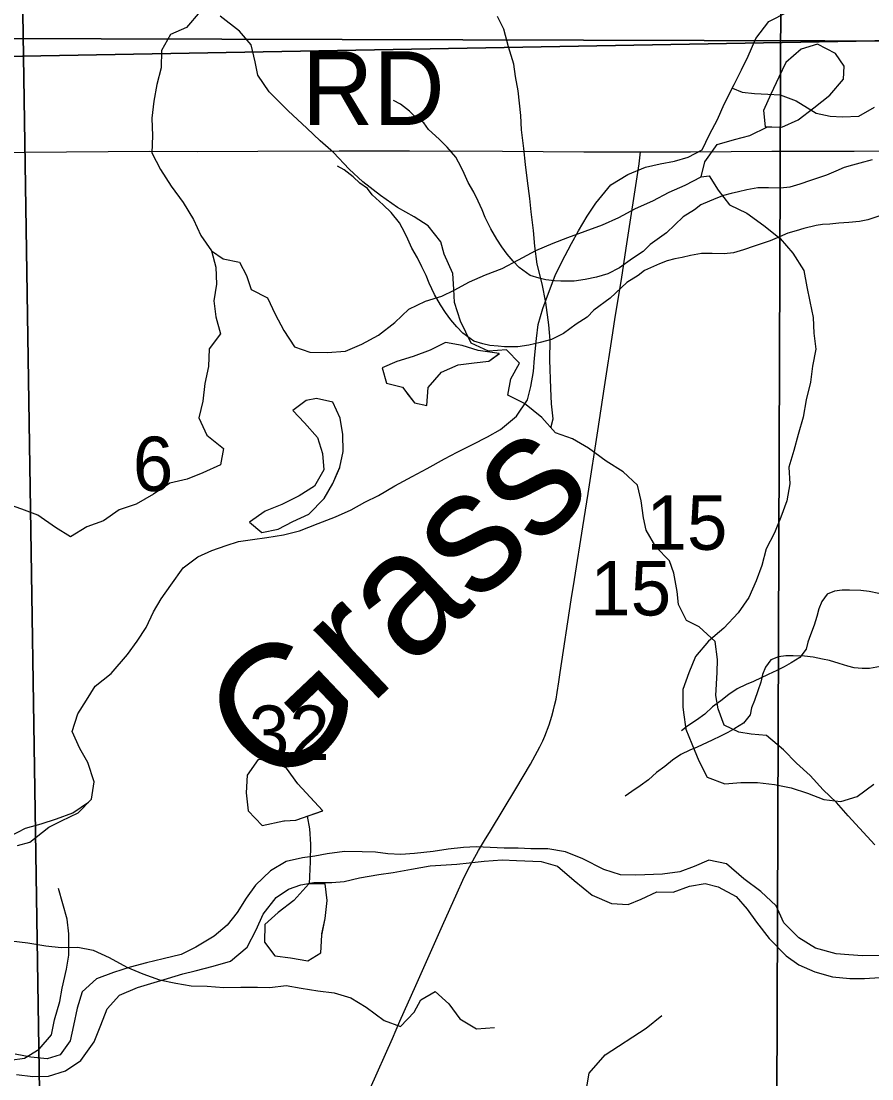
# Model space of a CAD drawing. Extents: x -21.1 to 50.3, y 0 to 22.1.
# Drawn here: x 5.83 to 6.485, y 16.143 to 16.957 of the extents above; entities that cross this region are included whole.
import ezdxf

# ---------------------------------------------------------------- set-up
doc = ezdxf.new("R2010")
doc.units = 0
for name, color, linetype in [('GM_X_Minor_Lake', 7, 'Continuous'), ('GM_X_Minor_River', 7, 'Continuous'), ('GM_X_Minor_River_Text', 7, 'Continuous'), ('GM_X_Section', 7, 'Continuous'), ('GM_X_Section_Text', 7, 'Continuous'), ('GM_X_Township_Road', 7, 'Continuous'), ('GM_X_Township_Road_Text', 7, 'Continuous')]:
    doc.layers.add(name, color=color, linetype=linetype)

msp = doc.modelspace()

# ---------------------------------------------------------------- linework, layer by layer
at = {"layer": 'GM_X_Minor_Lake'}
for points in [[(6.4637, 16.92197), (6.45706, 16.93166), (6.44297, 16.93887), (6.43042, 16.93505), (6.41864, 16.92477), (6.41333, 16.91335), (6.40726, 16.90042), (6.40157, 16.88786), (6.40273, 16.87532), (6.40788, 16.87519)], [(6.40788, 16.87519), (6.41567, 16.87496), (6.42821, 16.88067), (6.44038, 16.88982), (6.45254, 16.89972), (6.46317, 16.9119), (6.4637, 16.92197)], [(6.40788, 16.87517), (6.41567, 16.87496), (6.42821, 16.88067), (6.44038, 16.88982), (6.45254, 16.89972), (6.46317, 16.9119), (6.4637, 16.92197)], [(6.1982, 16.70081), (6.18192, 16.70317), (6.16974, 16.70696), (6.1568, 16.70923), (6.14501, 16.70351), (6.13208, 16.69855), (6.11953, 16.69473), (6.10813, 16.68978), (6.11157, 16.67799), (6.12375, 16.67496), (6.12713, 16.67047)], [(6.19822, 16.70081), (6.18192, 16.70317), (6.16974, 16.70696), (6.1568, 16.70923), (6.14501, 16.70351), (6.13208, 16.69855), (6.11953, 16.69473), (6.10813, 16.68978), (6.11157, 16.67799), (6.12375, 16.67496), (6.12713, 16.67047)], [(6.12708, 16.67042), (6.1329, 16.66281), (6.14241, 16.66092), (6.14353, 16.67461), (6.15379, 16.68641), (6.16672, 16.69213), (6.17889, 16.69367), (6.19031, 16.69482), (6.19829, 16.70088)], [(6.12713, 16.67047), (6.1329, 16.66281), (6.14241, 16.66092), (6.14353, 16.67461), (6.15379, 16.68641), (6.16672, 16.69213), (6.17889, 16.69367), (6.19031, 16.69482), (6.1982, 16.70081)], [(6.05765, 16.66625), (6.04957, 16.66461), (6.0393, 16.65699), (6.04845, 16.6475), (6.05836, 16.6361), (6.06218, 16.62394), (6.06335, 16.61139), (6.05613, 16.59883), (6.04435, 16.59122), (6.03104, 16.58473), (6.01811, 16.57939), (6.00595, 16.57102), (6.01547, 16.56304), (6.02803, 16.56572), (6.03943, 16.57144), (6.0516, 16.57716), (6.06338, 16.58934), (6.07021, 16.60075), (6.07379, 16.60922)], [(6.0576, 16.66624), (6.04957, 16.66461), (6.0393, 16.65699), (6.04845, 16.6475), (6.05836, 16.6361), (6.06218, 16.62394), (6.06335, 16.61139), (6.05613, 16.59883), (6.04435, 16.59122), (6.03104, 16.58473), (6.01811, 16.57939), (6.00595, 16.57102), (6.01547, 16.56304), (6.02803, 16.56572), (6.03943, 16.57144), (6.0516, 16.57716), (6.06338, 16.58934), (6.07021, 16.60075), (6.07547, 16.61319)], [(6.07547, 16.61319), (6.07552, 16.61331), (6.07816, 16.62548), (6.07776, 16.63841), (6.07584, 16.65095), (6.07011, 16.66349), (6.0576, 16.66624)], [(6.07378, 16.60922), (6.07552, 16.61331), (6.07816, 16.62548), (6.07776, 16.63841), (6.07584, 16.65095), (6.07011, 16.66349), (6.05772, 16.66621)], [(6.06239, 16.3489), (6.04316, 16.36954), (6.03439, 16.38169), (6.02297, 16.38738), (6.01269, 16.38851), (6.00434, 16.37633), (6.0036, 16.36264), (6.00514, 16.34896), (6.01581, 16.33756), (6.03246, 16.34109), (6.03301, 16.34126)], [(6.06216, 16.34915), (6.04316, 16.36954), (6.03439, 16.38169), (6.02297, 16.38738), (6.01269, 16.38851), (6.00434, 16.37633), (6.0036, 16.36264), (6.00514, 16.34896), (6.01581, 16.33756), (6.03246, 16.34109), (6.03291, 16.34123)], [(6.03285, 16.34125), (6.04168, 16.34178), (6.0623, 16.34887)], [(6.03301, 16.34126), (6.04168, 16.34178), (6.06239, 16.3489)], [(6.05163, 16.29275), (6.04025, 16.2798), (6.02809, 16.27065), (6.01783, 16.26152), (6.01747, 16.24783), (6.02547, 16.23719), (6.03765, 16.23568), (6.05097, 16.23342), (6.06086, 16.23952), (6.0616, 16.25321), (6.06186, 16.25449)], [(6.05162, 16.29274), (6.04025, 16.2798), (6.02809, 16.27065), (6.01783, 16.26152), (6.01747, 16.24783), (6.02547, 16.23719), (6.03765, 16.23568), (6.05097, 16.23342), (6.06086, 16.23952), (6.0616, 16.25321), (6.06186, 16.25449)], [(6.06186, 16.25449), (6.06424, 16.26614), (6.06574, 16.27983), (6.0642, 16.29275), (6.05162, 16.29274)], [(6.06178, 16.25421), (6.06424, 16.26614), (6.06574, 16.27983), (6.0642, 16.29275), (6.05165, 16.29274)]]:
    msp.add_lwpolyline(points, dxfattribs=at)
at = {"layer": 'GM_X_Minor_River'}
for points in [[(5.96807, 16.96413), (5.95744, 16.95157), (5.94527, 16.94623), (5.93844, 16.93405), (5.93808, 16.92074), (5.93467, 16.90781), (5.93241, 16.89488), (5.93091, 16.88195), (5.93131, 16.86826), (5.93095, 16.85533), (5.93744, 16.84241), (5.94583, 16.8295), (5.95498, 16.81696), (5.96299, 16.80404), (5.96871, 16.7915), (5.97672, 16.77972)], [(6.22539, 16.6973), (6.22676, 16.71247), (6.22807, 16.72309), (6.23168, 16.73557), (6.23604, 16.74728), (6.24119, 16.76088), (6.24629, 16.77144), (6.25373, 16.78538), (6.25919, 16.79518), (6.26583, 16.80647), (6.27244, 16.81663), (6.28405, 16.83051), (6.29709, 16.83866), (6.31085, 16.84415), (6.32191, 16.84665), (6.33295, 16.84876), (6.34364, 16.85201), (6.35436, 16.85755), (6.35986, 16.86924), (6.36612, 16.88092), (6.37124, 16.89262), (6.37907, 16.9077), (6.38456, 16.91901), (6.38966, 16.92957), (6.39557, 16.94315), (6.40565, 16.9563), (6.4202, 16.96367)], [(6.48713, 16.3226), (6.47545, 16.33558), (6.46678, 16.34512), (6.45774, 16.35541), (6.44756, 16.36496), (6.43739, 16.37603), (6.42683, 16.38558), (6.41703, 16.39588), (6.40382, 16.40697), (6.39206, 16.40779), (6.38258, 16.40937), (6.37124, 16.41475), (6.36676, 16.4273), (6.36493, 16.43756), (6.36581, 16.45538), (6.36625, 16.46524), (6.36445, 16.47929), (6.352, 16.49037), (6.34217, 16.49537), (6.33618, 16.50754), (6.3351, 16.51779), (6.33254, 16.53185), (6.32919, 16.54135), (6.31863, 16.55204), (6.31113, 16.56499), (6.30929, 16.57448), (6.30748, 16.5874), (6.30453, 16.59955), (6.29359, 16.60987), (6.28036, 16.61792), (6.26676, 16.62786), (6.25467, 16.63515), (6.24142, 16.63978), (6.23087, 16.65161), (6.21766, 16.66231), (6.2048, 16.66884), (6.20716, 16.68135), (6.21369, 16.69345), (6.20389, 16.70375), (6.18984, 16.7027), (6.1766, 16.70885), (6.16836, 16.7256), (6.1639, 16.74004), (6.16321, 16.75029), (6.16253, 16.76244), (6.1558, 16.77727), (6.15321, 16.78677), (6.14342, 16.79897), (6.13284, 16.80587), (6.11998, 16.81316), (6.10676, 16.82235), (6.09317, 16.83305), (6.08261, 16.8426), (6.07055, 16.85558), (6.06036, 16.86437), (6.05018, 16.87429), (6.03585, 16.88766), (6.02114, 16.90217), (6.0125, 16.91512), (6.01029, 16.92538), (6.00734, 16.9383), (5.9983, 16.94898), (5.98358, 16.96045)], [(6.23789, 16.64373), (6.23959, 16.65042), (6.23853, 16.66218), (6.23785, 16.67395), (6.23723, 16.69596), (6.23733, 16.71113), (6.23627, 16.7229), (6.23411, 16.73999), (6.23117, 16.75442), (6.22747, 16.76962), (6.22566, 16.78329), (6.22461, 16.79544), (6.2228, 16.80987), (6.22173, 16.82012), (6.21993, 16.83379), (6.21849, 16.84632), (6.21705, 16.85847), (6.21525, 16.8729), (6.21494, 16.8839), (6.21279, 16.90288), (6.21059, 16.9139), (6.20951, 16.92339), (6.20543, 16.93669), (6.20172, 16.95038), (6.19685, 16.96027)], [(6.37766, 16.90498), (6.38506, 16.90191), (6.39454, 16.90101), (6.40478, 16.90047), (6.41427, 16.89994), (6.42673, 16.8952), (6.44216, 16.88585), (6.45276, 16.88341), (6.46224, 16.88288), (6.47479, 16.88345), (6.48705, 16.89048)], [(6.23416, 16.75758), (6.22883, 16.75869), (6.22196, 16.76093), (6.21355, 16.76696), (6.20896, 16.77188), (6.20436, 16.77717), (6.20014, 16.78284), (6.1963, 16.7889), (6.19169, 16.79685), (6.18746, 16.80557), (6.18514, 16.81125), (6.18206, 16.81807), (6.17859, 16.82489), (6.17436, 16.83247), (6.17128, 16.83929), (6.16897, 16.84421), (6.16474, 16.85179), (6.15822, 16.85973), (6.1521, 16.86577), (6.14368, 16.87332), (6.14023, 16.87824), (6.13412, 16.88239), (6.12914, 16.8873), (6.12226, 16.89258), (6.11691, 16.89559)], [(6.3537, 16.83685), (6.35635, 16.84826), (6.36584, 16.86159), (6.37915, 16.8654), (6.39095, 16.86846), (6.40459, 16.87528)], [(6.48525, 16.84974), (6.47574, 16.84741), (6.47004, 16.84586), (6.46358, 16.84392), (6.45713, 16.84123), (6.44991, 16.83815), (6.44307, 16.83584), (6.43776, 16.83391), (6.4294, 16.8312), (6.4218, 16.82888), (6.41457, 16.82808), (6.40543, 16.82841), (6.39706, 16.82837), (6.38869, 16.8268), (6.38223, 16.82525), (6.37653, 16.82407), (6.37083, 16.82252), (6.36475, 16.82021), (6.35336, 16.81521), (6.34843, 16.81139), (6.33971, 16.80602), (6.32683, 16.79379), (6.31433, 16.78461), (6.30903, 16.77926), (6.30068, 16.7739), (6.29083, 16.76663), (6.28172, 16.76202), (6.27297, 16.75969), (6.26423, 16.75774), (6.25586, 16.75656), (6.24559, 16.7565), (6.24064, 16.75685), (6.23416, 16.75758)], [(6.19087, 16.70706), (6.18554, 16.70817), (6.17867, 16.71042), (6.17027, 16.71645), (6.16567, 16.72136), (6.16107, 16.72665), (6.15685, 16.73233), (6.15302, 16.73839), (6.1484, 16.74634), (6.14417, 16.75505), (6.14185, 16.76074), (6.13877, 16.76756), (6.1353, 16.77438), (6.13107, 16.78195), (6.12799, 16.78877), (6.12568, 16.7937), (6.12145, 16.80127), (6.11493, 16.80921), (6.10881, 16.81526), (6.10039, 16.82281), (6.09694, 16.82773), (6.09083, 16.83187), (6.08585, 16.83679), (6.07897, 16.84207), (6.07363, 16.84507)], [(5.97672, 16.77972), (5.98586, 16.77365), (5.99842, 16.77101), (6.00376, 16.76075), (6.0072, 16.7501), (6.01977, 16.74366), (6.02588, 16.73112), (6.03236, 16.71858), (6.04075, 16.70604), (6.05255, 16.70187), (6.06587, 16.70151), (6.07995, 16.70267), (6.0925, 16.70801), (6.10542, 16.71487), (6.11796, 16.72477), (6.1286, 16.73505), (6.14153, 16.74115), (6.15408, 16.74497), (6.16359, 16.74954), (6.17537, 16.75602), (6.18754, 16.76136), (6.20047, 16.76632), (6.21302, 16.7728), (6.22632, 16.78004), (6.23963, 16.78576), (6.25104, 16.78996), (6.27766, 16.79988), (6.29021, 16.80559), (6.30314, 16.81246), (6.31644, 16.81818), (6.32899, 16.82503), (6.34116, 16.83037), (6.3537, 16.83685)], [(6.3537, 16.83685), (6.35979, 16.83762), (6.36666, 16.8266), (6.37542, 16.81521), (6.38875, 16.80876), (6.4017, 16.79927), (6.41427, 16.7894), (6.42418, 16.77801), (6.43257, 16.76471), (6.43488, 16.75216), (6.43718, 16.74076), (6.43986, 16.7286), (6.44026, 16.71643), (6.4418, 16.70426), (6.43915, 16.69095), (6.43765, 16.67878), (6.43425, 16.66509), (6.43198, 16.65178), (6.4282, 16.63846), (6.42479, 16.62629), (6.42101, 16.61336), (6.42179, 16.60043), (6.41952, 16.5875), (6.41498, 16.57495), (6.41005, 16.56278), (6.4036, 16.5506), (6.40019, 16.53767), (6.39602, 16.52588), (6.39034, 16.51294), (6.38198, 16.50114), (6.37097, 16.48934), (6.35919, 16.47944), (6.34931, 16.46764), (6.344, 16.45509), (6.33946, 16.44215), (6.33948, 16.42884), (6.33986, 16.42466), (6.34179, 16.41174), (6.34637, 16.40033), (6.35171, 16.38741), (6.3582, 16.37487), (6.37191, 16.36957), (6.38408, 16.37072), (6.39702, 16.37074), (6.40996, 16.36924), (6.4229, 16.36659), (6.43546, 16.36242), (6.44802, 16.3575), (6.46096, 16.35599), (6.47351, 16.35981), (6.48644, 16.36933)], [(6.49178, 16.80709), (6.4819, 16.80362), (6.47544, 16.80245), (6.46707, 16.80164), (6.45946, 16.80122), (6.45261, 16.80042), (6.4469, 16.80001), (6.44196, 16.79922), (6.43245, 16.79689), (6.42675, 16.79534), (6.42029, 16.79341), (6.41384, 16.79071), (6.40662, 16.78764), (6.39978, 16.78532), (6.39447, 16.78339), (6.38611, 16.78068), (6.37851, 16.77837), (6.37128, 16.77757), (6.36214, 16.7779), (6.35377, 16.77785), (6.3454, 16.77629), (6.33894, 16.77473), (6.33324, 16.77356), (6.32754, 16.77201), (6.32146, 16.7697), (6.31007, 16.7647), (6.30514, 16.76087), (6.29642, 16.7555), (6.28355, 16.74328), (6.27104, 16.73409), (6.26574, 16.72875), (6.25739, 16.72338), (6.24754, 16.71611), (6.23843, 16.7115), (6.22969, 16.70917), (6.22094, 16.70723), (6.21258, 16.70604), (6.2023, 16.70598), (6.19735, 16.70634), (6.19087, 16.70706)], [(5.97672, 16.77972), (5.98016, 16.76718), (5.98056, 16.75425), (5.97868, 16.74132), (5.98022, 16.72916), (5.98366, 16.71586), (5.97493, 16.70444), (5.97457, 16.69075), (5.97155, 16.67782), (5.97004, 16.66413), (5.96702, 16.6512), (5.97313, 16.63789), (5.98608, 16.62764), (5.98382, 16.61509), (5.97013, 16.60899), (5.95796, 16.60403), (5.94464, 16.60098), (5.9321, 16.5926), (5.9188, 16.58498), (5.90587, 16.5804), (5.8937, 16.57202), (5.88077, 16.56744), (5.86823, 16.55982), (5.8568, 16.56703), (5.84309, 16.57651), (5.83091, 16.58106), (5.80426, 16.59015)], [(5.82759, 16.32233), (5.83712, 16.32484), (5.85173, 16.3364), (5.8613, 16.34119), (5.87431, 16.34745), (5.88435, 16.35794), (5.88646, 16.3712), (5.88175, 16.38609), (5.87546, 16.39682), (5.86959, 16.40982), (5.87398, 16.42343), (5.8806, 16.43397), (5.88722, 16.44488), (5.89953, 16.45457), (5.91229, 16.46919), (5.91966, 16.47934), (5.92666, 16.48987), (5.93217, 16.50194), (5.93802, 16.51211), (5.9454, 16.52263), (5.9551, 16.53578), (5.96625, 16.54435), (5.97696, 16.54912), (5.98804, 16.55313), (5.99758, 16.55603), (6.00824, 16.55777), (6.01928, 16.55912), (6.03222, 16.5612), (6.04443, 16.56443), (6.05895, 16.56991), (6.07232, 16.57503), (6.08418, 16.58054), (6.09491, 16.58646), (6.10524, 16.59162), (6.11789, 16.59903), (6.1313, 16.60604), (6.14279, 16.61233), (6.1562, 16.61972), (6.16577, 16.62489), (6.17764, 16.63079), (6.18912, 16.63669), (6.19909, 16.64224), (6.2114, 16.65269), (6.21995, 16.66509), (6.22239, 16.67531), (6.22447, 16.68706), (6.22539, 16.6973)], [(6.49016, 16.51624), (6.48292, 16.51772), (6.47644, 16.51844), (6.46769, 16.51877), (6.46198, 16.51874), (6.45627, 16.51795), (6.45058, 16.51564), (6.44642, 16.50992), (6.44417, 16.50421), (6.44268, 16.4985), (6.44043, 16.49165), (6.43781, 16.48442), (6.43556, 16.47871), (6.43445, 16.47339), (6.42954, 16.4669), (6.42271, 16.46269), (6.4174, 16.45962), (6.4117, 16.45693), (6.40525, 16.45385), (6.39386, 16.44847), (6.38816, 16.44616)], [(6.49144, 16.45989), (6.48307, 16.45832), (6.47736, 16.45829), (6.47127, 16.45902), (6.46632, 16.46013), (6.45983, 16.46237), (6.45221, 16.46461), (6.44687, 16.46572), (6.43963, 16.4672), (6.43316, 16.46793), (6.4244, 16.46826), (6.41869, 16.46822), (6.41299, 16.46743), (6.40729, 16.46512), (6.40313, 16.4594), (6.40088, 16.45369), (6.39939, 16.44799), (6.39715, 16.44114), (6.39452, 16.43391), (6.39227, 16.42819), (6.39116, 16.42287), (6.38625, 16.41639), (6.37942, 16.41217), (6.37411, 16.4091), (6.36841, 16.40641), (6.36196, 16.40334), (6.35057, 16.39796), (6.34487, 16.39565)], [(6.38816, 16.44616), (6.38133, 16.44271), (6.37488, 16.43849), (6.36882, 16.43352), (6.36238, 16.42893), (6.35632, 16.4232), (6.34987, 16.4186), (6.34343, 16.41439), (6.3385, 16.41056)], [(6.34487, 16.39565), (6.33804, 16.39219), (6.3316, 16.38798), (6.32553, 16.38301), (6.31909, 16.37841), (6.31303, 16.37268), (6.30658, 16.36809), (6.30014, 16.36387), (6.29521, 16.36005)], [(5.75797, 16.24865), (5.75492, 16.25359), (5.75109, 16.26727), (5.74993, 16.27944), (5.75067, 16.29313), (5.75941, 16.30454), (5.7731, 16.30874), (5.78527, 16.31256), (5.79782, 16.31714), (5.80923, 16.32286), (5.82177, 16.32934), (5.83356, 16.33543), (5.84573, 16.33887), (5.85752, 16.34269), (5.87007, 16.34727), (5.88223, 16.35565)], [(6.0503, 16.34475), (6.05221, 16.33509), (6.05307, 16.32331), (6.05278, 16.30962), (6.05207, 16.29279)], [(6.49074, 16.2376), (6.47784, 16.23729), (6.46722, 16.23812), (6.45736, 16.23894), (6.44145, 16.24321), (6.4286, 16.25126), (6.41729, 16.26271), (6.4113, 16.27565), (6.39961, 16.28672), (6.3864, 16.29667), (6.37319, 16.30813), (6.35954, 16.31087), (6.34813, 16.30601), (6.3371, 16.3019), (6.3238, 16.30009), (6.3033, 16.29946), (6.29154, 16.29953), (6.27867, 16.30378), (6.2624, 16.31185), (6.24916, 16.31724), (6.23551, 16.3196), (6.22261, 16.31968), (6.21275, 16.32012), (6.20212, 16.32019), (6.19112, 16.32063), (6.1805, 16.32108), (6.17063, 16.32076), (6.15885, 16.31932), (6.14746, 16.31749)], [(6.14746, 16.31749), (6.13303, 16.31606), (6.1224, 16.31537), (6.11253, 16.31581), (6.10305, 16.317), (6.09281, 16.31745), (6.07915, 16.31753), (6.06585, 16.31572), (6.05635, 16.31388), (6.04686, 16.3128), (6.03432, 16.30984), (6.02212, 16.30271), (6.01067, 16.29177), (6.00339, 16.28158), (5.99649, 16.27062), (5.98883, 16.2608), (5.97891, 16.25251), (5.96481, 16.24387), (5.95339, 16.23825), (5.93971, 16.23492), (5.92678, 16.23197), (5.91424, 16.22863), (5.90131, 16.22454), (5.88837, 16.21968), (5.8773, 16.20951), (5.87342, 16.19701), (5.87068, 16.18375), (5.86794, 16.17201), (5.86028, 16.16105), (5.8504, 16.15808), (5.83788, 16.15929), (5.82575, 16.16164)], [(5.82679, 16.14608), (5.8393, 16.14449), (5.85145, 16.14479), (5.86438, 16.14888), (5.87619, 16.15678), (5.88653, 16.17113), (5.89155, 16.184), (5.89657, 16.19649), (5.90613, 16.20705), (5.91983, 16.21304), (5.93276, 16.21676), (5.94302, 16.21973), (5.95481, 16.22345), (5.96431, 16.22566), (5.978, 16.22937), (5.99131, 16.23309), (6.00428, 16.24401), (6.0112, 16.25725), (6.01659, 16.26935), (6.02654, 16.28219), (6.03607, 16.28858), (6.04558, 16.29194), (6.05546, 16.29377), (6.0695, 16.29369), (6.07899, 16.29439), (6.09078, 16.29735), (6.10559, 16.29991), (6.11661, 16.30137), (6.13067, 16.30393)], [(6.13067, 16.30393), (6.14511, 16.3065), (6.16561, 16.30789), (6.1751, 16.30897), (6.18649, 16.31004), (6.20054, 16.31109), (6.21154, 16.31064), (6.23051, 16.30977), (6.24301, 16.30628), (6.25584, 16.29519), (6.26981, 16.28411), (6.28457, 16.27756), (6.29746, 16.27673), (6.30736, 16.28084), (6.31954, 16.28645), (6.33206, 16.28638), (6.34461, 16.29085), (6.35677, 16.29306), (6.36662, 16.29034), (6.38061, 16.28304), (6.3889, 16.27313), (6.39604, 16.26322), (6.40582, 16.25064), (6.41902, 16.23728), (6.42884, 16.23039), (6.44095, 16.225), (6.45458, 16.22112), (6.46786, 16.2199), (6.47924, 16.21983), (6.49101, 16.22052)], [(5.82188, 16.15701), (5.8329, 16.15859), (5.84429, 16.16549), (5.85374, 16.17656), (5.85596, 16.18797), (5.86007, 16.20205), (5.86191, 16.21231), (5.86526, 16.22715), (5.8671, 16.23779), (5.86701, 16.25413), (5.8658, 16.26552), (5.86231, 16.27727), (5.8592, 16.28903)], [(5.82265, 16.24873), (5.83559, 16.24722), (5.84929, 16.24496), (5.86109, 16.24383), (5.87403, 16.24385), (5.88582, 16.24158), (5.89801, 16.23589), (5.91172, 16.22868), (5.9239, 16.22338), (5.93685, 16.21883), (5.94941, 16.21618), (5.96121, 16.2143), (5.97338, 16.21393), (5.98632, 16.21281), (5.99925, 16.2132), (6.01219, 16.21322), (6.02171, 16.21285), (6.03426, 16.21439), (6.04568, 16.2125), (6.05862, 16.21024), (6.07118, 16.20873), (6.08412, 16.20494), (6.09592, 16.19773), (6.10964, 16.18748), (6.1222, 16.18294), (6.13284, 16.19398), (6.13777, 16.20349), (6.14879, 16.20997), (6.15946, 16.20047), (6.16785, 16.1887), (6.1808, 16.18111), (6.1945, 16.18227)], [(6.22986, 16.04361), (6.24193, 16.05144), (6.24986, 16.06173), (6.26007, 16.07509), (6.2657, 16.08803), (6.26639, 16.10095), (6.26554, 16.11614), (6.26433, 16.12905), (6.26728, 16.14692), (6.27976, 16.16105), (6.31123, 16.18173), (6.32336, 16.1913)]]:
    msp.add_lwpolyline(points, dxfattribs=at)
at = {"layer": 'GM_X_Section'}
for points in [[(5.48815, 17.97251), (6.51666, 17.95921), (6.54146, 16.94121), (5.52017, 16.94387)], [(5.77564, 17.94152), (6.7924, 17.96396), (6.8008, 16.94709), (5.78818, 16.92886)], [(5.45266, 17.13084), (6.41542, 17.12601), (6.41187, 16.12459), (5.44952, 16.13321)], [(6.47301, 17.12604), (7.40705, 17.13199), (7.42125, 16.12212), (6.41187, 16.12459), (6.41542, 17.12601)], [(5.83147, 16.97938), (6.84408, 16.99761), (6.85861, 15.97246), (5.84702, 15.96751)], [(4.84683, 16.96859), (5.83147, 16.97938), (5.84702, 15.96751), (4.86162, 15.95861)], [(5.78818, 16.92886), (6.8008, 16.94709), (6.81532, 15.92194), (5.80373, 15.91699)], [(6.54146, 16.94121), (6.55964, 15.91994), (6.50469, 15.92066), (5.53343, 15.91957), (5.52017, 16.94387)]]:
    msp.add_lwpolyline(points, close=True, dxfattribs=at)
at = {"layer": 'GM_X_Township_Road'}
for points in [[(5.78428, 16.85548), (5.8331, 16.85566), (5.92926, 16.8564), (5.96641, 16.85631), (6.01235, 16.8565), (6.07497, 16.85666), (6.12908, 16.85679), (6.20059, 16.85643), (6.26335, 16.85611), (6.30681, 16.85589), (6.34537, 16.85604), (6.40799, 16.85645), (6.47131, 16.85655), (6.5041, 16.85666), (6.52846, 16.85674)], [(6.08171, 16.09681), (6.11597, 16.1736), (6.12179, 16.18694), (6.13412, 16.21451), (6.15464, 16.2606), (6.16574, 16.28582), (6.17022, 16.29546), (6.17459, 16.30443), (6.17787, 16.31047), (6.18222, 16.31844), (6.1869, 16.32605), (6.19152, 16.33358), (6.21103, 16.36575), (6.22213, 16.38492), (6.22953, 16.39826), (6.23166, 16.40263), (6.23334, 16.40644), (6.2367, 16.41496), (6.23867, 16.4217), (6.24008, 16.42654), (6.24085, 16.42988), (6.24194, 16.43483), (6.24287, 16.43985), (6.2441, 16.44803), (6.24508, 16.45543), (6.25363, 16.51115), (6.2561, 16.52685), (6.2626, 16.56732), (6.26652, 16.59298), (6.27415, 16.6413), (6.27919, 16.67516), (6.28573, 16.71674), (6.28752, 16.72869), (6.29215, 16.75769), (6.2959, 16.78176), (6.30579, 16.84686), (6.30681, 16.85589)]]:
    msp.add_lwpolyline(points, dxfattribs=at)

# ---------------------------------------------------------------- texts
at = {"layer": 'GM_X_Minor_River_Text'}
msp.add_text('Grass', height=0.094725, rotation=43.46303, dxfattribs=at).set_placement((6.02734, 16.36164))
at = {"layer": 'GM_X_Section_Text'}
for s, height, p in [('6', 0.04186, (5.91628, 16.59498)), ('15', 0.041856, (6.31151, 16.54974)), ('15', 0.041856, (6.26822, 16.49922)), ('32', 0.041856, (6.00553, 16.38807))]:
    msp.add_text(s, height=height, rotation=0.00001, dxfattribs=at).set_placement(p)
at = {"layer": 'GM_X_Township_Road_Text'}
msp.add_text('RD', height=0.056818, rotation=0.00001, dxfattribs=at).set_placement((6.04647, 16.87665))

doc.saveas('drawing.dxf')
